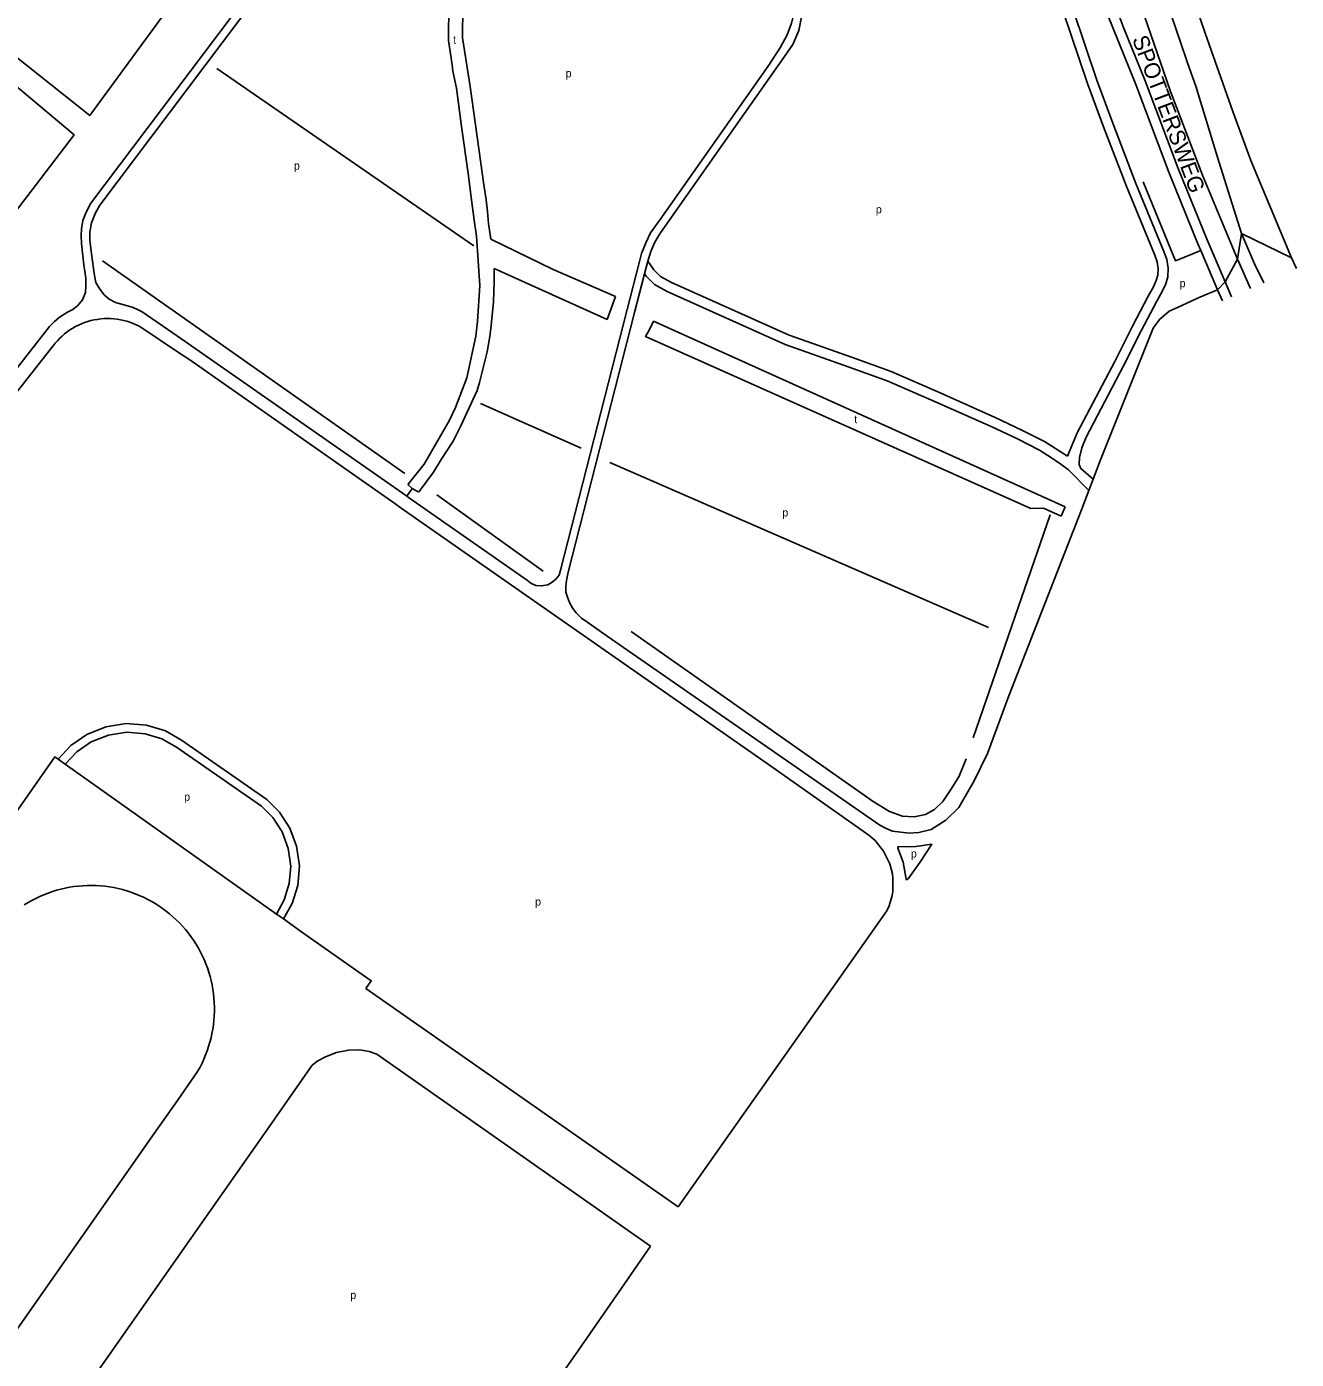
# Model space of a CAD drawing. Extents: x 153608 to 155459, y 385052 to 386919.
# Drawn here: x 154825 to 155459, y 385587 to 386253 of the extents above; entities that cross this region are included whole.
import ezdxf

# ---------------------------------------------------------------- set-up
doc = ezdxf.new("R2010")
doc.units = 0
for name, color, linetype in [('BLT_Basislijn', 7, 'Continuous'), ('BLT_Centroide', 7, 'Continuous'), ('BLT_Straatnaam_hoofdweg', 7, 'Continuous'), ('BLT_Vlakafsluiter', 7, 'Continuous')]:
    doc.layers.add(name, color=color, linetype=linetype)

msp = doc.modelspace()

# ---------------------------------------------------------------- linework, layer by layer
at = {"layer": 'BLT_Basislijn'}
for p, q in [((154988.92, 386340.45), (154856.63, 386164.91)), ((154992.12, 386338.05), (154861.19, 386164)), ((154919.57, 386232.31), (155048.19, 386143.59)), ((155419.79, 386188.42), (155432.07, 386149.73)), ((155396.6, 386141.83), (155382.9, 386175.6)), ((155131.93, 386139.88), (155130.95, 386135.83)), ((154862.49, 386136.21), (155013.7, 386029.84)), ((155135.16, 386136), (155133.49, 386129.64)), ((155430.03, 386136.96), (155436.46, 386122.26)), ((155423.77, 386125.58), (155427.04, 386118.17)), ((155411.18, 386117.96), (155400, 386112.9)), ((155411.18, 386117.96), (155420.02, 386121.7)), ((155422.46, 386116.18), (155420.02, 386121.7)), ((155137.93, 386106.04), (155135.87, 386101.48)), ((155137.93, 386106.04), (155343.91, 386013.17)), ((154674.74, 385886.78), (154837.72, 386093.56)), ((155101.81, 386042.54), (155051.41, 386064.77)), ((155305.42, 385952.84), (155116.1, 386035.4)), ((155345.45, 386031.66), (155355.65, 386021.31)), ((155361.45, 386036.66), (155357.78, 386026.94)), ((155357.78, 386026.94), (155355.65, 386021.31)), ((155017.37, 386022.36), (155014.67, 386018.51)), ((155029.58, 386019.12), (155082.76, 385981.02)), ((155355.65, 386021.31), (155352.02, 386011.67)), ((155074.97, 385976.39), (155016.01, 386017.57)), ((155343.91, 386013.17), (155341.86, 386008.61)), ((155336.4, 386009.13), (155297.88, 385897.68)), ((154899.46, 385893.09), (154941.97, 385863.56)), ((154901.98, 385896.64), (154944.7, 385866.87)), ((154840.32, 385887.12), (154843.87, 385884.6)), ((154949.49, 385809.67), (154952.99, 385807.19)), ((155150.34, 385663.26), (154994.11, 385772.43)), ((154909.97, 385730.89), (154901.88, 385719.14))]:
    msp.add_line(p, q, dxfattribs=at)
for points in [[(155311.39, 386555.07), (155329.18, 386482.51), (155332.53, 386462.84), (155335.01, 386445.27), (155342.29, 386406.16), (155344.69, 386393.43), (155350.43, 386368.15), (155355.78, 386347.41), (155375.09, 386282.84), (155396.54, 386220.76), (155412.59, 386179.01), (155430.03, 386136.96)], [(155330.05, 386398.02), (155336.58, 386374.16), (155343.14, 386349.47), (155350.01, 386324.21), (155354.34, 386309.41), (155365.28, 386275.09), (155368.07, 386266.65), (155372.73, 386253.67), (155383.82, 386226.12), (155400.38, 386182.24), (155414.84, 386146.62), (155423.77, 386125.58)], [(155068.22, 386372.34), (155067.79, 386368.72), (155066.79, 386362.68), (155061.44, 386344.05), (155056.54, 386326.32), (155050.38, 386304.46), (155048.1, 386295.14), (155043.34, 386272.71), (155042.6, 386263.09), (155042.51, 386247.58), (155046.3, 386223.24), (155049.85, 386198.18), (155051.59, 386185.01), (155053.06, 386175.24), (155054.24, 386166.67), (155055.06, 386160.8), (155055.5, 386154.74), (155056.65, 386147.04)], [(155051.82, 386332.55), (155051.71, 386332.14), (155050.69, 386328.57), (155048.84, 386320.9), (155042.19, 386296.02), (155041.46, 386293.81), (155036.74, 386273.43), (155035.65, 386264.6), (155035.46, 386246.32), (155037.24, 386234.18)], [(155400, 386249.74), (155396.23, 386261.07), (155392.53, 386272.42), (155388.91, 386283.79), (155385.36, 386295.18), (155382.14, 386305.78)], [(155400, 386290.55), (155400.3, 386289.55), (155413.76, 386250)], [(155340.26, 386283.74), (155340.53, 386274.4), (155341.22, 386267.76), (155342.69, 386261.21), (155354.96, 386224.85), (155362.97, 386203.19), (155374.61, 386172.99), (155388.6, 386138.97), (155389.84, 386135.62), (155390.34, 386132.31), (155390.13, 386128.97), (155389.39, 386126.33), (155387.94, 386123.08), (155385.3, 386118.5)], [(155411.63, 386141.39), (155410.22, 386144.7), (155395.72, 386180.41), (155379.16, 386224.31), (155364.75, 386260.11), (155360.21, 386272.98)], [(155208.23, 386259.65), (155207, 386254.95), (155204.87, 386249.19), (155201.46, 386243), (155195.58, 386234)], [(155212.23, 386259.01), (155210.63, 386251.33), (155207.64, 386244.28), (155202.31, 386236.6), (155197.2, 386229.35)], [(155347.67, 386262.1), (155359.68, 386226.52), (155367.65, 386204.95), (155379.25, 386174.84), (155393.25, 386140.79), (155394.71, 386136.88), (155395.36, 386132.52), (155395.09, 386128.13), (155394.1, 386124.62), (155392.4, 386120.81), (155389.63, 386116.01)], [(155419.79, 386188.42), (155409.11, 386223.41), (155405.15, 386234.67), (155401.28, 386245.96), (155400, 386249.74)], [(155413.76, 386250), (155427.73, 386210.86), (155436.75, 386186.31), (155457.07, 386137.63)], [(155037.24, 386234.18), (155037.7, 386230.97), (155039.47, 386222.43), (155042.02, 386203.34), (155045.32, 386179.85), (155046.98, 386166.67), (155048.26, 386156.5), (155049.5, 386148.53), (155051.09, 386123.83), (155050.01, 386105.77), (155049.14, 386098.53), (155044.6, 386077.64), (155038.95, 386062.88), (155035.86, 386056.2), (155023.27, 386034.49), (155015.33, 386024.52), (155015.49, 386024.05), (155017.37, 386022.36)], [(155141.26, 386156.81), (155195.58, 386234)], [(155143.77, 386153.43), (155197.2, 386229.35)], [(154707.16, 385938.62), (154835.97, 386103.38), (154838.35, 386105.66), (154840.9, 386108.05), (154844.93, 386110.45), (154847.62, 386111.79), (154850.16, 386113.89), (154852.4, 386116.73), (154853.9, 386120.32), (154854.2, 386123.31), (154854.2, 386127.49), (154853.15, 386134.07), (154852.4, 386140.21), (154851.96, 386144.84), (154851.81, 386148.88), (154851.96, 386152.17), (154852.7, 386156.36), (154854.35, 386160.54), (154856.63, 386164.91)], [(154861.19, 386164), (154858.98, 386160.1), (154857.04, 386155.16), (154856.14, 386150.52), (154856.14, 386146.49), (154857.04, 386139.61), (154857.79, 386133.48), (154858.39, 386128.84), (154859.13, 386125.25), (154861.08, 386121.96), (154863.32, 386119.12), (154865.86, 386117.03), (154869, 386115.38), (154871.99, 386114.48), (154874.98, 386113.74), (154877.82, 386112.84), (154880.36, 386111.64), (154882.37, 386110.62)], [(155141.26, 386156.81), (155136.48, 386150.1), (155134.4, 386145.53), (155131.93, 386139.88)], [(155135.16, 386136), (155136.66, 386140.8), (155138.73, 386145.56), (155141.11, 386149.7), (155143.77, 386153.43)], [(155056.65, 386147.04), (155087.85, 386131.8), (155119.06, 386118.35)], [(155443.17, 386125.18), (155438.53, 386134.64), (155432.07, 386149.73)], [(155396.6, 386141.83), (155398.97, 386136.19), (155411.63, 386141.39)], [(155420.02, 386121.7), (155419.18, 386123.59), (155411.63, 386141.39)], [(155457.07, 386137.63), (155459.44, 386132.25)], [(155019.09, 386021.29), (155020.3, 386020.65), (155020.87, 386020.84), (155027.97, 386030.5), (155031.87, 386036.83), (155037.74, 386045.99), (155041.73, 386053.61), (155049.77, 386071.4), (155050.93, 386075.38), (155054.82, 386090.66), (155056.11, 386098.29), (155056.83, 386103.79), (155057.95, 386115.71), (155058.24, 386125.72), (155058.24, 386132.39)], [(155058.24, 386132.39), (155114.8, 386106.83), (155119.06, 386118.35)], [(155124.82, 386111.88), (155130.95, 386135.83)], [(155135.16, 386136), (155138.14, 386131.71), (155141.51, 386128.34), (155147.06, 386125.39), (155205.75, 386099.01), (155237.56, 386087.77), (155256.76, 386080.78), (155281.4, 386070.11), (155308.9, 386057.82), (155322.12, 386051.59), (155333.53, 386045.82), (155344.97, 386038.56)], [(155128.54, 386110.25), (155133.49, 386129.64)], [(155133.49, 386129.64), (155134.29, 386128.49), (155138.51, 386124.27), (155144.86, 386120.9), (155203.89, 386094.36), (155235.88, 386083.07), (155254.91, 386076.13), (155279.38, 386065.54), (155306.82, 386053.27), (155319.93, 386047.1), (155331.05, 386041.47), (155337.5, 386037.38), (155341.71, 386034.53), (155345.45, 386031.66)], [(155385.3, 386118.5), (155377.48, 386103.51), (155368.62, 386085.91), (155349.87, 386050.15), (155344.97, 386038.56)], [(155091.46, 385981.48), (155124.82, 386111.88)], [(155389.63, 386116.01), (155381.92, 386101.2), (155373.07, 386083.62), (155354.39, 386048.02), (155352.14, 386042.68), (155350.95, 386037.85), (155350.9, 386034.31), (155351.71, 386032.43), (155357.78, 386026.94)], [(155400, 386112.9), (155395.76, 386110.98), (155390.98, 386106.84), (155387.9, 386102.45)], [(154882.21, 386102.67), (154880.77, 386103.47), (154879.28, 386104.19), (154877.77, 386104.84), (154876.22, 386105.42), (154874.65, 386105.92), (154873.05, 386106.35), (154871.44, 386106.7), (154869.81, 386106.97), (154868.17, 386107.16), (154866.52, 386107.27), (154864.87, 386107.3), (154863.22, 386107.25), (154861.58, 386107.12), (154859.94, 386106.91), (154858.31, 386106.62), (154856.7, 386106.26), (154855.11, 386105.81), (154853.54, 386105.29), (154852, 386104.7), (154850.49, 386104.03), (154849.02, 386103.29), (154847.58, 386102.47), (154846.19, 386101.59), (154844.83, 386100.65), (154843.53, 386099.63), (154842.27, 386098.56), (154841.07, 386097.43), (154839.93, 386096.24), (154838.85, 386094.99), (154837.82, 386093.7), (154837.72, 386093.56)], [(154882.37, 386110.62), (154900, 386098.58), (155012.34, 386020.14), (155014.67, 386018.51)], [(155095.37, 385980.6), (155128.54, 386110.25)], [(154882.21, 386102.67), (154900, 386090.66), (154906.1, 386086.66), (155008.61, 386014.82), (155011.86, 386012.56)], [(155135.87, 386101.48), (155134.03, 386098.29), (155326.75, 386012.38), (155332.93, 386012.47), (155341.86, 386008.61)], [(155387.9, 386102.45), (155361.45, 386036.66)], [(155014.67, 386018.51), (155016.01, 386017.57)], [(155017.37, 386022.36), (155019.09, 386021.29)], [(155011.86, 386012.56), (155197.7, 385882.87), (155245.62, 385849.07), (155248.91, 385846.35), (155253.05, 385841.04), (155256.24, 385834.67), (155257.42, 385829.74), (155257.67, 385827.36), (155257.62, 385820.92), (155257.35, 385818.91), (155255.76, 385813.72), (155254.64, 385811.33), (155238.05, 385787.64), (155176.11, 385700), (155150.34, 385663.26)], [(155352.02, 386011.67), (155315.69, 385918.79), (155304.95, 385889.98), (155298.32, 385876.17), (155290.67, 385862.85), (155284.24, 385856.52), (155276.87, 385851.93), (155270.66, 385850.36), (155265.91, 385850.01), (155257.57, 385851.12), (155254.07, 385852.5), (155251.21, 385854.1), (155114.78, 385948.59), (155105.14, 385955.32)], [(155091.46, 385981.48), (155090.75, 385979.07), (155089.23, 385976.99), (155087.29, 385975.46), (155085.08, 385974.22), (155081.89, 385973.66), (155079.12, 385973.94), (155076.63, 385975.05), (155074.97, 385976.39)], [(155095.37, 385980.6), (155094.49, 385976.43), (155094.08, 385973.39), (155094.21, 385970.48), (155095.18, 385967.57), (155096.15, 385965.07), (155097.68, 385962.44), (155099.34, 385960.23), (155101.97, 385957.59), (155105.14, 385955.32)], [(155126.82, 385950.86), (155247.87, 385865.93), (155255.93, 385860.98), (155262.42, 385858.62), (155268.39, 385858.31), (155273.92, 385859.39), (155278.57, 385861.87), (155282.63, 385865.93), (155286.96, 385872.35), (155290.9, 385878.65), (155294.39, 385887.23)], [(154840.32, 385887.12), (154846.63, 385893.86), (154854.7, 385899.45), (154864.16, 385903.26), (154874.38, 385904.84), (154884.55, 385904.06), (154893.93, 385901.17), (154901.98, 385896.64)], [(154843.87, 385884.6), (154849.58, 385890.66), (154856.86, 385895.67), (154865.4, 385899.08), (154874.6, 385900.49), (154883.76, 385899.78), (154892.21, 385897.17), (154899.46, 385893.09)], [(154840.32, 385887.12), (154838.7, 385888.27), (154736.7, 385742.49)], [(154949.49, 385809.67), (154843.87, 385884.6)], [(154944.7, 385866.87), (154950.98, 385860.56), (154956.11, 385852.65), (154959.54, 385843.51), (154960.9, 385833.71), (154960.09, 385823.98), (154957.31, 385814.97), (154952.99, 385807.19)], [(154941.97, 385863.56), (154947.64, 385857.85), (154952.27, 385850.72), (154955.37, 385842.47), (154956.61, 385833.63), (154955.88, 385824.84), (154953.37, 385816.71), (154949.49, 385809.67)], [(155271.12, 385835.46), (155265.31, 385827.3), (155264.58, 385826.78), (155264.26, 385827.09), (155262.81, 385835.57), (155260.1, 385842.65), (155260.17, 385843.29), (155269.13, 385843.43), (155277.1, 385844.61), (155271.12, 385835.46)], [(154823.36, 385814.2), (154825.26, 385815.36), (154827.19, 385816.46), (154829.17, 385817.48), (154831.18, 385818.44), (154833.22, 385819.32), (154835.29, 385820.12), (154837.39, 385820.85), (154839.52, 385821.51), (154841.66, 385822.08), (154843.83, 385822.58), (154846.01, 385823.01), (154848.21, 385823.35), (154850.42, 385823.61), (154852.63, 385823.8), (154854.85, 385823.9), (154857.08, 385823.93), (154859.3, 385823.87), (154861.52, 385823.73), (154863.73, 385823.52), (154865.93, 385823.22), (154868.13, 385822.85), (154870.3, 385822.4), (154872.46, 385821.87), (154874.6, 385821.26), (154876.72, 385820.58), (154878.81, 385819.82), (154880.87, 385818.98), (154882.9, 385818.07), (154884.89, 385817.09), (154886.85, 385816.04), (154888.77, 385814.92), (154890.65, 385813.73), (154892.48, 385812.47), (154894.27, 385811.15), (154896.01, 385809.77), (154897.7, 385808.32), (154899.33, 385806.81), (154900.91, 385805.25), (154902.44, 385803.63), (154903.9, 385801.95), (154905.3, 385800.23), (154906.64, 385798.45), (154907.91, 385796.63), (154909.12, 385794.76), (154910.26, 385792.85), (154911.33, 385790.91), (154912.33, 385788.92), (154913.26, 385786.9), (154914.12, 385784.85), (154914.9, 385782.76), (154915.6, 385780.66), (154916.23, 385778.52), (154916.78, 385776.37), (154917.25, 385774.2), (154917.65, 385772.01), (154917.96, 385769.81), (154918.2, 385767.6), (154918.36, 385765.38), (154918.43, 385763.16), (154918.43, 385760.93), (154918.35, 385758.71), (154918.18, 385756.49), (154917.94, 385754.28), (154917.62, 385752.08), (154917.22, 385749.9), (154916.74, 385747.73), (154916.18, 385745.57), (154915.55, 385743.44), (154914.84, 385741.33), (154914.05, 385739.25), (154913.19, 385737.2), (154912.26, 385735.19), (154911.26, 385733.2), (154910.18, 385731.26), (154909.97, 385730.89)], [(154961.5, 385801.15), (154952.99, 385807.19)], [(154994.11, 385772.43), (154996.85, 385776.35), (154961.5, 385801.15)], [(155136.54, 385643.59), (154999.72, 385739.54), (154995.76, 385741.02), (154991.18, 385741.78), (154985.52, 385741.68), (154979.5, 385740.41), (154973.92, 385738.29), (154970.21, 385736.24), (154967.32, 385734.16)], [(155009.26, 385461.55), (154900.77, 385538.19), (154900, 385538.38), (154853.52, 385571.74), (154900, 385638.05), (154943.41, 385700), (154967.32, 385734.16)], [(154901.88, 385719.14), (154900, 385716.45), (154888.39, 385700), (154816.71, 385597.68), (154770, 385630.39)], [(155136.54, 385643.59), (155123.43, 385624.89), (155099.06, 385589.47), (155009.26, 385461.55)]]:
    msp.add_lwpolyline(points, dxfattribs=at)
for points in [[(154856.58, 386359.27), (154783.71, 386266.32), (154856.11, 386208.79), (154924.13, 386301.7)], [(154777.49, 386258.49), (154724.3, 386184.63), (154724.27, 386176.18), (154782.89, 386130.91), (154796.43, 386131.44), (154848.23, 386199.21)]]:
    msp.add_lwpolyline(points, close=True, dxfattribs=at)
at = {"layer": 'BLT_Vlakafsluiter'}
for p, q in [((155430.03, 386136.96), (155432.07, 386149.73)), ((155432.07, 386149.73), (155457.07, 386137.63)), ((155430.03, 386136.96), (155423.77, 386125.58)), ((155423.77, 386125.58), (155420.02, 386121.7))]:
    msp.add_line(p, q, dxfattribs=at)

# ---------------------------------------------------------------- texts
at = {"layer": 'BLT_Centroide'}
for s, p in [('t', (155037.75, 386244.69)), ('p', (155094.05, 386227.89)), ('p', (154958.18, 386181.74)), ('p', (155249.15, 386159.88)), ('p', (155401.04, 386122.95)), ('t', (155238.38, 386055.02)), ('p', (155202.41, 386008.36)), ('p', (154903.29, 385866.29)), ('p', (155266.68, 385837.9)), ('p', (155078.79, 385813.88)), ('p', (154986.37, 385617.25))]:
    msp.add_text(s, height=4, dxfattribs=at).set_placement(p)
at = {"layer": 'BLT_Straatnaam_hoofdweg'}
msp.add_text('SPOTTERSWEG', height=8, rotation=290.7, dxfattribs=at).set_placement((155377.2, 386247.06))

doc.saveas('drawing.dxf')
